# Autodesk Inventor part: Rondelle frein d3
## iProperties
Author: Flavien MARTY
Shininess: 60.0
PropertySet Name: _Private Model Information
Created: 2001-10
Part Number: Rondelle frein d3
Material: Par défaut
Document SubType Name: Modélisation
Designer: Flavien MARTY
Control State: 0
Master: False
Checked Out: False
PropertySet Name: Design Tracking Control
Density: 0.0
Volumn: 0.0
Area: 0.0
PropertySet Name: Model Information
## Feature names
1. Base1
